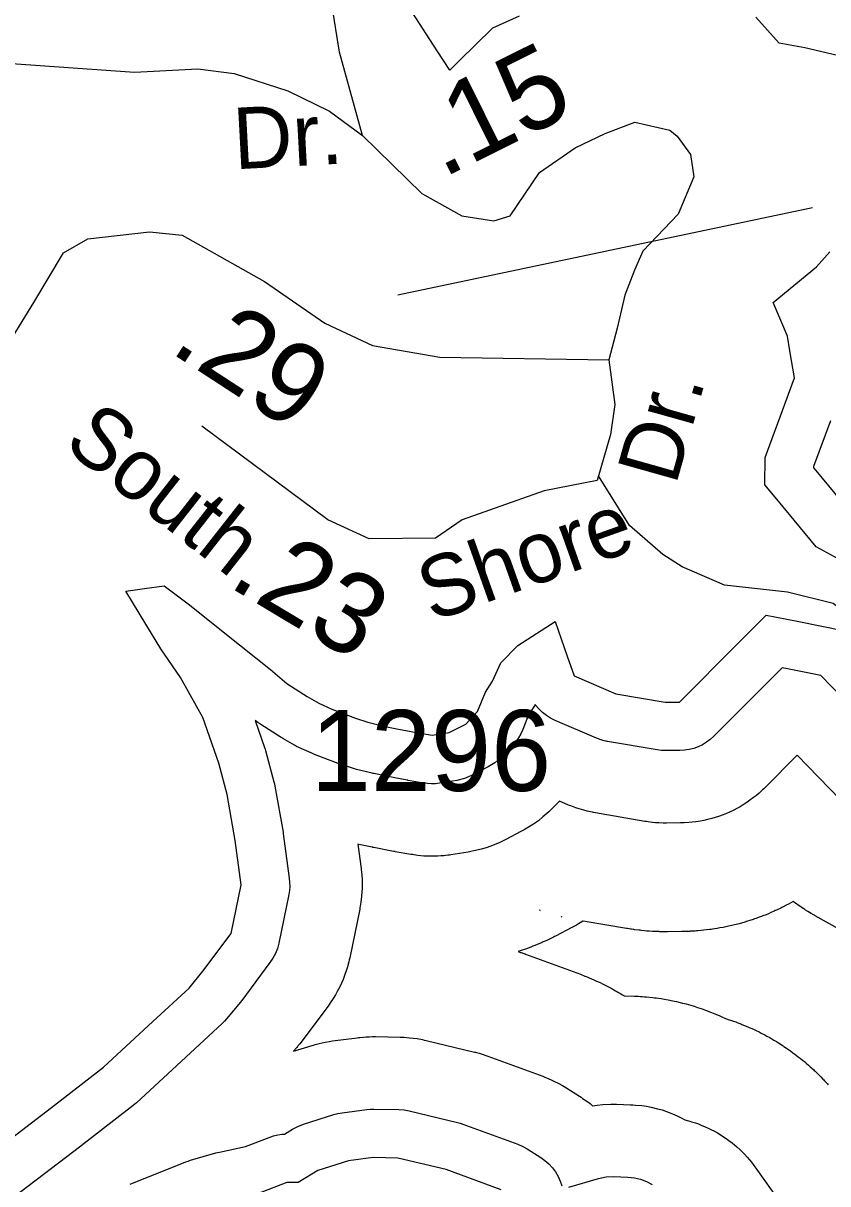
# Model space of a CAD drawing. Extents: x 1113032 to 1302912, y 664689 to 832535.
# Drawn here: x 1149593 to 1150837, y 736082 to 737877 of the extents above; entities that cross this region are included whole.
import ezdxf

# ---------------------------------------------------------------- set-up
doc = ezdxf.new("R2010")
doc.units = 0
for name, color, linetype in [('Exist Hydrographic Buffer Line', 7, 'Continuous'), ('Exist Hydrographic Lake Shore', 7, 'Continuous'), ('Exist Road Non-System Type 51', 7, 'Continuous'), ('Exist Road Secondary Mileage Hundredths English Label', 7, 'Continuous'), ('Exist Road Secondary Type 51 Attributed', 7, 'Continuous'), ('Exist Road Secondary Type 51 Label', 7, 'Continuous'), ('Exist Road Secondary Type 51 Number Label', 7, 'Continuous')]:
    doc.layers.add(name, color=color, linetype=linetype)

msp = doc.modelspace()

# ---------------------------------------------------------------- linework, layer by layer
at = {"layer": 'Exist Hydrographic Buffer Line'}
for points in [[(1150840.6, 737262), (1150814.5, 737191.6), (1150814.5, 737189.5), (1150817.9, 737185.4), (1150866.9, 737126.1)], [(1150858.4, 736834.5), (1150825.6, 736868.2), (1150774.4, 736878.4), (1150766, 736880.1), (1150750.4, 736864.4), (1150660.3, 736774.2), (1150654.9, 736769.3), (1150649.1, 736764.9), (1150642.8, 736761.2), (1150636.3, 736758), (1150629.4, 736755.5), (1150622.4, 736753.7), (1150615.2, 736752.6), (1150607.9, 736752.2), (1150586, 736752), (1150579.3, 736752.2), (1150572.6, 736753.1), (1150496.1, 736766.2), (1150494.6, 736766.5), (1150493.1, 736766.8), (1150491, 736767.3), (1150488.9, 736767.8), (1150487.5, 736768.3), (1150486, 736768.6), (1150484, 736769.4), (1150481.9, 736770.1), (1150480.5, 736770.7), (1150479.1, 736771.2), (1150415, 736798.8), (1150408, 736802.3), (1150401.5, 736806.4), (1150395.4, 736811.1), (1150389.8, 736816.5), (1150384.8, 736822.4), (1150384.1, 736823.5), (1150384, 736823.1), (1150380.9, 736818.1), (1150373.9, 736807.5), (1150364.9, 736784.8), (1150361.9, 736778.2), (1150358.3, 736772), (1150354.1, 736766.2), (1150349.4, 736760.8), (1150330.8, 736741.4), (1150321.7, 736733.3), (1150311.4, 736726.8), (1150285.7, 736713.4), (1150274.6, 736708.7), (1150262.8, 736705.8), (1150236.4, 736701.6), (1150230.2, 736700.9), (1150223.9, 736700.7), (1150217.7, 736701), (1150211.5, 736701.8), (1150187.5, 736706.1), (1150187, 736706.2), (1150186.4, 736706.3), (1150156.1, 736712.1), (1150155.5, 736712.2), (1150155, 736712.3), (1150134.5, 736716.6), (1150133.4, 736716.8), (1150132.3, 736717.1), (1150107.9, 736722.9), (1150104.8, 736723.7), (1150101.7, 736724.7), (1150082.9, 736730.9), (1150081.3, 736731.5), (1150079.7, 736732), (1150042.9, 736746.1), (1150040.8, 736747), (1150038.7, 736747.9), (1150018.6, 736757), (1150015.2, 736758.6), (1150012, 736760.4), (1149993.9, 736770.9), (1149992.6, 736771.6), (1149991.3, 736772.4), (1149959.8, 736792.5), (1149955.1, 736795.6), (1149951.3, 736798.8), (1149965.7, 736757), (1149966.5, 736754.5), (1149967.3, 736752), (1149980.3, 736703.8), (1149981.1, 736700.6), (1149981.8, 736697.3), (1149994.3, 736626.2), (1149994.5, 736624.7), (1149994.7, 736623.2), (1150004, 736554.6), (1150004.5, 736548.3), (1150004.6, 736542), (1150004.1, 736535.7), (1150003.1, 736529.5), (1149987.6, 736454.2), (1149985.5, 736446.2), (1149982.5, 736438.5), (1149978.7, 736431.2), (1149974.1, 736424.3), (1149930.4, 736365.9), (1149929.3, 736364.6), (1149928.3, 736363.2), (1149906.9, 736337.4), (1149903.6, 736333.6), (1149900, 736330), (1149843.8, 736278), (1149843.8, 736277.9), (1149843.8, 736277.9), (1149767.7, 736207.5), (1149765.2, 736205.3), (1149762.7, 736203.2), (1149682.2, 736141), (1149682, 736140.8), (1149681.8, 736140.7), (1149578, 736061.5)], [(1150855.8, 736676.5), (1150789.3, 736744.9), (1150739.6, 736695.1), (1150737.6, 736693.2), (1150735.6, 736691.3), (1150730.2, 736686.4), (1150726.1, 736682.9), (1150721.8, 736679.5), (1150716, 736675.2), (1150711.6, 736672), (1150707, 736669.1), (1150700.8, 736665.3), (1150696, 736662.6), (1150691.2, 736660.2), (1150684.6, 736657), (1150679.7, 736654.8), (1150674.6, 736652.8), (1150667.8, 736650.3), (1150662.6, 736648.6), (1150657.4, 736647.1), (1150650.3, 736645.3), (1150645, 736644), (1150639.7, 736643.1), (1150632.5, 736642), (1150627.1, 736641.2), (1150621.7, 736640.8), (1150614.4, 736640.4), (1150611.7, 736640.3), (1150609, 736640.2), (1150587, 736640), (1150584.5, 736640), (1150582, 736640.1), (1150575.3, 736640.3), (1150570.3, 736640.6), (1150565.3, 736641.1), (1150558.6, 736641.9), (1150556.1, 736642.3), (1150553.7, 736642.7), (1150477.2, 736655.8), (1150474.5, 736656.3), (1150472.5, 736656.7), (1150469.8, 736657.2), (1150464.6, 736658.4), (1150464.6, 736658.5), (1150464.5, 736658.5), (1150464.4, 736658.5), (1150464.4, 736658.5), (1150459.3, 736659.8), (1150455.7, 736660.9), (1150452, 736661.9), (1150447, 736663.7), (1150447, 736663.7), (1150446.9, 736663.7), (1150446.8, 736663.7), (1150446.8, 736663.7), (1150441.8, 736665.5), (1150439.3, 736666.6), (1150437.4, 736667.3), (1150434.8, 736668.3), (1150421.5, 736674.1), (1150411.7, 736663.9), (1150408.5, 736660.7), (1150405.2, 736657.6), (1150396, 736649.5), (1150389, 736643.7), (1150381.4, 736638.5), (1150371.1, 736632), (1150367.2, 736629.7), (1150363.2, 736627.5), (1150337.6, 736614.1), (1150333.5, 736612.1), (1150329.4, 736610.2), (1150318.2, 736605.5), (1150309.7, 736602.3), (1150301, 736599.8), (1150289.3, 736597), (1150284.8, 736596), (1150280.4, 736595.2), (1150253.9, 736591), (1150251.6, 736590.6), (1150249.3, 736590.3), (1150243.1, 736589.6), (1150238.5, 736589.2), (1150233.8, 736588.9), (1150227.6, 736588.7), (1150222.9, 736588.7), (1150218.3, 736588.8), (1150212, 736589.1), (1150207.4, 736589.5), (1150202.7, 736590), (1150196.5, 736590.8), (1150194.2, 736591.2), (1150191.9, 736591.5), (1150167.9, 736595.8), (1150167.7, 736595.8), (1150167.5, 736595.9), (1150167, 736596), (1150166.6, 736596), (1150166.2, 736596.1), (1150165.6, 736596.2), (1150165.4, 736596.3), (1150165.2, 736596.3), (1150134.9, 736602.1), (1150134.7, 736602.2), (1150134.5, 736602.2), (1150134, 736602.3), (1150133.6, 736602.4), (1150133.2, 736602.5), (1150132.6, 736602.6), (1150132.5, 736602.6), (1150132.3, 736602.7), (1150111.7, 736606.9), (1150111.3, 736607), (1150110.9, 736607.1), (1150109.9, 736607.3), (1150115, 736569.6), (1150115.2, 736567.2), (1150115.5, 736564.9), (1150116.1, 736558.6), (1150116.4, 736553.9), (1150116.5, 736549.2), (1150116.6, 736542.9), (1150116.5, 736538.2), (1150116.2, 736533.5), (1150115.8, 736527.2), (1150115.3, 736522.5), (1150114.7, 736517.8), (1150113.6, 736511.6), (1150113.2, 736509.3), (1150112.8, 736507), (1150097.3, 736431.7), (1150096.6, 736428.6), (1150095.9, 736425.7), (1150093.8, 736417.7), (1150092.1, 736411.8), (1150090, 736405.9), (1150087, 736398.2), (1150084.7, 736392.5), (1150082, 736387), (1150078.2, 736379.7), (1150075.2, 736374.3), (1150071.9, 736369), (1150067.3, 736362.2), (1150065.6, 736359.6), (1150063.8, 736357.1), (1150020, 736298.8), (1150019.6, 736298.2), (1150019.2, 736297.7), (1150018.2, 736296.4), (1150017.4, 736295.4), (1150016.6, 736294.4), (1150015.5, 736293), (1150015.1, 736292.5), (1150014.7, 736292), (1150010.6, 736287.1), (1150039.2, 736296.1), (1150041.5, 736296.8), (1150043.8, 736297.5), (1150050.1, 736299.1), (1150054.8, 736300.3), (1150059.6, 736301.2), (1150066, 736302.4), (1150068.3, 736302.8), (1150070.7, 736303.1), (1150108.9, 736308.2), (1150111, 736308.5), (1150113.1, 736308.7), (1150118.7, 736309.2), (1150122.9, 736309.5), (1150127.2, 736309.7), (1150132.8, 736309.8), (1150134.9, 736309.8), (1150137, 736309.8), (1150175.5, 736309.1), (1150178.5, 736309), (1150181.6, 736308.8), (1150189.7, 736308.2), (1150195.7, 736307.6), (1150201.7, 736306.7), (1150209.8, 736305.2), (1150212.7, 736304.6), (1150215.7, 736303.9), (1150290.3, 736286), (1150291.9, 736285.6), (1150293.5, 736285.2), (1150297.7, 736284), (1150300.8, 736283.1), (1150303.9, 736282.2), (1150308, 736280.8), (1150309.6, 736280.3), (1150311.1, 736279.7), (1150396.1, 736248.5), (1150398.9, 736247.4), (1150401.6, 736246.3), (1150408.9, 736243.2), (1150414.2, 736240.7), (1150419.5, 736238), (1150426.4, 736234.1), (1150428.9, 736232.6), (1150431.4, 736231.1), (1150452.5, 736217.8), (1150455.1, 736216.1), (1150457.5, 736214.4), (1150464.1, 736209.8), (1150468.9, 736206.2), (1150472.8, 736202.9), (1150480, 736204.1), (1150488.9, 736204.8), (1150500.9, 736205.4), (1150505.4, 736205.5), (1150509.9, 736205.4), (1150531.6, 736204.6), (1150535.3, 736204.4), (1150539, 736204.1), (1150548.9, 736203.1), (1150556.2, 736202.1), (1150563.5, 736200.6), (1150573.1, 736198.3), (1150580.3, 736196.4), (1150587.3, 736194), (1150596.5, 736190.4), (1150603.4, 736187.5), (1150610, 736184.2), (1150615.7, 736181.1), (1150621, 736179.7), (1150623.3, 736179), (1150625.6, 736178.3), (1150631.8, 736176.3), (1150636.4, 736174.8), (1150641, 736173), (1150647, 736170.5), (1150651.4, 736168.5), (1150655.8, 736166.4), (1150661.6, 736163.4), (1150665.8, 736161), (1150670, 736158.5), (1150675.5, 736155), (1150679.5, 736152.3), (1150683.4, 736149.4), (1150688.6, 736145.5), (1150692.4, 736142.4), (1150696, 736139.2), (1150700.8, 736134.8), (1150704.4, 736131.5), (1150707.7, 736128), (1150712.1, 736123.2), (1150715.3, 736119.5), (1150718.4, 736115.7), (1150722.4, 736110.6), (1150723.8, 736108.6), (1150725.2, 736106.7), (1150761.7, 736054.7)], [(1150918.8, 736440.1), (1150817.1, 736496.7), (1150815.8, 736497.5), (1150814.5, 736498.3), (1150810.9, 736500.3), (1150808.3, 736501.9), (1150805.7, 736503.5), (1150802.2, 736505.6), (1150801, 736506.5), (1150799.7, 736507.3), (1150790.6, 736513.3), (1150788, 736515), (1150785.5, 736516.7), (1150782.8, 736518.7), (1150779.4, 736516.8), (1150775.8, 736514.8), (1150772.2, 736512.9), (1150767.4, 736510.4), (1150765.5, 736509.5), (1150763.7, 736508.6), (1150757.1, 736505.5), (1150755.3, 736504.6), (1150753.4, 736503.8), (1150748.5, 736501.5), (1150744.7, 736499.9), (1150741, 736498.4), (1150735.9, 736496.4), (1150734, 736495.7), (1150732.1, 736494.9), (1150725.2, 736492.5), (1150723.3, 736491.8), (1150721.4, 736491.1), (1150716.2, 736489.4), (1150712.4, 736488.1), (1150708.4, 736487), (1150703.2, 736485.5), (1150701.3, 736484.9), (1150699.3, 736484.4), (1150692.2, 736482.6), (1150690.3, 736482.1), (1150688.3, 736481.6), (1150683, 736480.4), (1150679, 736479.5), (1150675, 736478.7), (1150669.6, 736477.8), (1150667.6, 736477.4), (1150665.6, 736477.1), (1150658.4, 736476), (1150656.4, 736475.7), (1150654.4, 736475.4), (1150649, 736474.7), (1150644.9, 736474.2), (1150640.9, 736473.8), (1150635.5, 736473.4), (1150633.4, 736473.2), (1150631.4, 736473.1), (1150624.1, 736472.7), (1150623.1, 736472.6), (1150622.1, 736472.6), (1150619.4, 736472.4), (1150617.3, 736472.3), (1150615.3, 736472.3), (1150612.6, 736472.2), (1150611.6, 736472.2), (1150610.5, 736472.2), (1150588.6, 736472), (1150587.7, 736472), (1150586.7, 736472), (1150584.2, 736472), (1150582.3, 736472), (1150580.4, 736472), (1150577.9, 736472.1), (1150577, 736472.1), (1150576, 736472.2), (1150569.3, 736472.4), (1150567.5, 736472.5), (1150565.6, 736472.6), (1150560.6, 736472.9), (1150556.8, 736473.1), (1150553.1, 736473.5), (1150548.1, 736474), (1150546.2, 736474.2), (1150544.3, 736474.4), (1150537.7, 736475.2), (1150536.7, 736475.4), (1150535.8, 736475.5), (1150533.3, 736475.8), (1150531.4, 736476.1), (1150529.6, 736476.4), (1150527.1, 736476.8), (1150526.2, 736476.9), (1150525.2, 736477.1), (1150458.5, 736488.5), (1150457.8, 736488.1), (1150453.9, 736485.8), (1150450.9, 736484), (1150448, 736482.4), (1150444, 736480.2), (1150442.5, 736479.3), (1150440.9, 736478.5), (1150415.3, 736465.2), (1150413.8, 736464.4), (1150412.3, 736463.6), (1150408.2, 736461.6), (1150405.2, 736460.1), (1150402.1, 736458.7), (1150398, 736456.9), (1150396.4, 736456.2), (1150394.8, 736455.5), (1150383.7, 736450.8), (1150380.5, 736449.5), (1150377.4, 736448.3), (1150368.9, 736445.1), (1150362.5, 736442.8), (1150357.7, 736441.3), (1150361.4, 736440.1), (1150361.9, 736439.9), (1150362.5, 736439.7), (1150364.1, 736439.2), (1150365.2, 736438.8), (1150366.4, 736438.4), (1150367.9, 736437.8), (1150368.5, 736437.6), (1150369, 736437.4), (1150454, 736406.2), (1150455.1, 736405.8), (1150456.1, 736405.4), (1150458.9, 736404.4), (1150460.9, 736403.5), (1150463, 736402.7), (1150465.7, 736401.6), (1150466.7, 736401.2), (1150467.7, 736400.7), (1150475, 736397.6), (1150477, 736396.7), (1150479.1, 736395.8), (1150484.4, 736393.4), (1150488.4, 736391.4), (1150492.4, 736389.4), (1150497.6, 736386.7), (1150499.6, 736385.6), (1150501.5, 736384.6), (1150508.4, 736380.7), (1150509.4, 736380.2), (1150510.3, 736379.6), (1150512.9, 736378.1), (1150514.8, 736377), (1150516.7, 736375.9), (1150519.2, 736374.3), (1150520.1, 736373.8), (1150521.1, 736373.2), (1150521.2, 736373.1), (1150537.5, 736372.5), (1150538.9, 736372.5), (1150540.3, 736372.4), (1150544, 736372.2), (1150546.8, 736372), (1150549.6, 736371.8), (1150553.3, 736371.5), (1150554.7, 736371.4), (1150556, 736371.3), (1150565.9, 736370.2), (1150568.7, 736369.9), (1150571.4, 736369.6), (1150578.8, 736368.6), (1150584.3, 736367.8), (1150589.7, 736366.7), (1150597, 736365.3), (1150599.7, 736364.7), (1150602.4, 736364.1), (1150612.1, 736361.8), (1150614.8, 736361.1), (1150617.5, 736360.4), (1150624.6, 736358.4), (1150629.9, 736356.9), (1150635.2, 736355.1), (1150642.2, 736352.7), (1150644.8, 736351.8), (1150647.5, 736350.8), (1150656.7, 736347.3), (1150659.3, 736346.2), (1150661.9, 736345.2), (1150668.7, 736342.3), (1150673.8, 736340.1), (1150678.5, 736337.8), (1150682.6, 736336.5), (1150684.3, 736335.9), (1150686, 736335.4), (1150690.6, 736333.8), (1150694.1, 736332.6), (1150697.5, 736331.3), (1150702, 736329.5), (1150703.7, 736328.8), (1150705.4, 736328.2), (1150711.4, 736325.7), (1150713.1, 736324.9), (1150714.8, 736324.2), (1150719.2, 736322.3), (1150722.5, 736320.8), (1150725.8, 736319.2), (1150730.2, 736317), (1150731.8, 736316.2), (1150733.4, 736315.4), (1150739.2, 736312.4), (1150740.8, 736311.5), (1150742.4, 736310.6), (1150746.7, 736308.3), (1150749.9, 736306.5), (1150753, 736304.6), (1150757.2, 736302.1), (1150758.7, 736301.2), (1150760.3, 736300.2), (1150765.8, 736296.7), (1150767.3, 736295.7), (1150768.8, 736294.7), (1150772.8, 736292), (1150775.9, 736289.9), (1150778.8, 736287.8), (1150782.7, 736284.9), (1150784.2, 736283.9), (1150785.7, 736282.8), (1150790.8, 736278.8), (1150792.3, 736277.7), (1150793.7, 736276.5), (1150797.5, 736273.5), (1150800.3, 736271.2), (1150803.1, 736268.8), (1150806.7, 736265.6), (1150808.1, 736264.4), (1150809.5, 736263.2), (1150814.3, 736258.8), (1150815.6, 736257.5), (1150816.9, 736256.3), (1150820.4, 736252.9), (1150823, 736250.4), (1150825.6, 736247.8), (1150829, 736244.3), (1150830.2, 736242.9), (1150831.5, 736241.6), (1150835.9, 736236.8), (1150837.1, 736235.5)], [(1149758, 736081.5), (1149844, 736116.2), (1149847.5, 736117.5), (1149851.2, 736118.6), (1149890.3, 736130), (1149893.1, 736130.7), (1149895.8, 736131.3), (1149936, 736139.7), (1149972.6, 736154.1), (1149979.3, 736156.3), (1149986.2, 736157.9), (1149993.1, 736158.9), (1149996.4, 736159.1), (1150009, 736166.8), (1150017.1, 736171.1), (1150025.7, 736174.4), (1150072.9, 736189.3), (1150079.1, 736191), (1150085.5, 736192.1), (1150123.7, 736197.2), (1150129.3, 736197.7), (1150134.9, 736197.8), (1150173.4, 736197.1), (1150181.5, 736196.5), (1150189.5, 736195), (1150264.2, 736177.1), (1150268.4, 736176), (1150272.5, 736174.6), (1150357.5, 736143.4), (1150364.8, 736140.2), (1150371.7, 736136.4), (1150392.8, 736123), (1150399.3, 736118.4), (1150405.3, 736113.1), (1150410.7, 736107.2), (1150415.5, 736100.7), (1150419.5, 736093.8), (1150422.8, 736086.4), (1150425.1, 736079.3)], [(1150436.4, 736077.1), (1150482.2, 736090.5), (1150493.9, 736092.9), (1150505.9, 736093.5), (1150527.6, 736092.7), (1150537.5, 736091.7), (1150547.2, 736089.4), (1150556.4, 736085.8), (1150565.1, 736081.1)]]:
    msp.add_lwpolyline(points, dxfattribs=at)
for points in [[(1150391.7, 736505), (1150391.3, 736505.2), (1150390.9, 736505.3)], [(1150425.2, 736495.2), (1150424.7, 736495.3), (1150424.3, 736495.4)]]:
    msp.add_lwpolyline(points, close=True, dxfattribs=at)
at = {"layer": 'Exist Hydrographic Lake Shore'}
for points in [[(1150359.5, 737887.6), (1150318, 737869.3), (1150267, 737818.9), (1150252, 737804), (1150232.5, 737834.1), (1150193.8, 737894.1)], [(1151003.2, 737791.4), (1150800.8, 737838.5), (1150761.5, 737845.9), (1150725.1, 737886.2)], [(1150869.8, 737039.3), (1150818.4, 737067), (1150760.1, 737137.6), (1150739.4, 737162.8), (1150739.6, 737205.2), (1150770.2, 737288), (1150785.2, 737328.6), (1150778, 737370.3), (1150774.1, 737393), (1150752.3, 737445), (1150819.1, 737500.3), (1150839.7, 737523.3)], [(1149527.6, 736117.4), (1149636.3, 736200.3), (1149716.8, 736262.5), (1149792.9, 736333), (1149849, 736385), (1149870.4, 736410.9), (1149914.1, 736469.3), (1149929.6, 736544.6), (1149920.4, 736613.2), (1149907.9, 736684.3), (1149894.9, 736732.5), (1149870.4, 736803.2), (1149850.9, 736838.5), (1149836, 736865.3), (1149805.4, 736909.5), (1149782.3, 736947.6), (1149751.3, 736998.6), (1149780.1, 737002.7), (1149810.3, 737007), (1149849.5, 736977.7), (1149904.5, 736933.8), (1149975, 736877.4), (1150000, 736855.8), (1150031.5, 736835.7), (1150049.6, 736825.3), (1150069.7, 736816.2), (1150106.5, 736802.1), (1150125.3, 736795.9), (1150149.7, 736790), (1150170.3, 736785.8), (1150200.6, 736779.9), (1150224.6, 736775.7), (1150251, 736779.9), (1150276.7, 736793.2), (1150295.2, 736812.6), (1150307.1, 736842.4), (1150318.3, 736859.3), (1150331.2, 736887.8), (1150357.4, 736914.4), (1150414.9, 736951.8), (1150433.8, 736898.2), (1150444.6, 736867.7), (1150508.8, 736840.1)], [(1150508.8, 736840.1), (1150585.3, 736827), (1150607.2, 736827.2), (1150697.3, 736917.5), (1150741.4, 736961.5), (1150789.1, 736952), (1150863.1, 736937.1)], [(1150331.6, 736073), (1150246.6, 736104.2), (1150172, 736122.1), (1150133.5, 736122.8), (1150095.4, 736117.8), (1150048.2, 736102.9), (1150017.8, 736084.2), (1150000, 736084.2), (1149957.5, 736067.6)]]:
    msp.add_lwpolyline(points, dxfattribs=at)
at = {"layer": 'Exist Road Non-System Type 51'}
msp.add_lwpolyline([(1151101.4, 736808.6), (1151051.7, 736820.1), (1150844.7, 736979.3), (1150774, 736997), (1150676.7, 737007.8), (1150611.5, 737036.4), (1150581.6, 737055.4), (1150530, 737100.3), (1150482, 737177.1)], dxfattribs=at)
at = {"layer": 'Exist Road Secondary Type 51 Attributed'}
for points in [[(1150117.2, 737703.4), (1150081.7, 737832.1), (1150057.8, 737980.9), (1150073.7, 738066.9), (1150099.4, 738097.6), (1150142.9, 738183.6), (1150182.7, 738245.2)], [(1149347.8, 736882.3), (1149287.7, 736897.5), (1149219.8, 736911.6), (1149133.9, 736916.8), (1149131.4, 736936), (1149150.4, 736956), (1149183.9, 736997.6), (1149196.7, 737032.2), (1149219.8, 737070.7), (1149259.5, 737119.4), (1149312.1, 737219.5), (1149383.6, 737421.7), (1149387.5, 737487.6), (1149438.9, 737706.1), (1149473.5, 737767.5), (1149530.4, 737801.8), (1149574.9, 737814.7), (1149764.4, 737801), (1149862.6, 737806.3), (1149918.6, 737798.9), (1150001.8, 737772.3), (1150066, 737740.6), (1150117.2, 737703.4)], [(1150117.2, 737703.4), (1150209.1, 737613.3), (1150270.7, 737578.9), (1150320.4, 737571.3), (1150345.4, 737579), (1150391, 737645.8), (1150446.2, 737684.3), (1150492.3, 737706.1), (1150538.4, 737724), (1150592.3, 737711.2), (1150603.8, 737702.2), (1150624.3, 737674), (1150629.5, 737639.4), (1150605.1, 737581.6), (1150550.7, 737524.5), (1150537.8, 737495), (1150522.5, 737456.5), (1150510.9, 737405.2), (1150498.1, 737356.4)], [(1149347.8, 736882.3), (1149367, 736973.4), (1149404.2, 737082.4), (1149429.9, 737165.8), (1149476.9, 737247.3), (1149530.8, 737317.9), (1149609, 737444.9), (1149655.1, 737521.8), (1149692.3, 737543.6), (1149787.7, 737554.4), (1149838.4, 737548.8), (1149965.7, 737477.3), (1150058.9, 737412.8), (1150132.7, 737378.4), (1150236.6, 737360.3), (1150498.1, 737356.4)], [(1150498.1, 737356.4), (1150507.1, 737287.2), (1150500.7, 737241), (1150479.9, 737169.8), (1150398.1, 737153.8), (1150271.2, 737108.9), (1150230.2, 737080.7), (1150127.7, 737079.4), (1150063.6, 737108.9), (1149868.7, 737253.8)]]:
    msp.add_lwpolyline(points, dxfattribs=at)
at = {"layer": 'Exist Road Secondary Type 51 Number Label'}
msp.add_line((1150171.6, 737456.6), (1150812.9, 737591.6), dxfattribs=at)

# ---------------------------------------------------------------- texts
at = {"layer": 'Exist Road Secondary Mileage Hundredths English Label'}
for s, rotation, p in [('.15', 26.4566, (1150240.8, 737636.5)), ('.29', 326.973, (1149816.6, 737369.8)), ('.23', 329.1069, (1149906.7, 737007.6))]:
    msp.add_text(s, height=125, rotation=rotation, dxfattribs=at).set_placement(p)
at = {"layer": 'Exist Road Secondary Type 51 Label'}
for s, rotation, p in [('Dr.', 3.0623, (1149919.5, 737650.8)), ('Dr.', 74.2715, (1150601.4, 737160.7)), ('South', 321.8777, (1149652.3, 737222.5)), ('Shore', 19.5842, (1150224.3, 736950.6))]:
    msp.add_text(s, height=95, rotation=rotation, dxfattribs=at).set_placement(p)
at = {"layer": 'Exist Road Secondary Type 51 Number Label'}
msp.add_text('1296', height=125, dxfattribs=at).set_placement((1150037, 736689.8))

doc.saveas('drawing.dxf')
